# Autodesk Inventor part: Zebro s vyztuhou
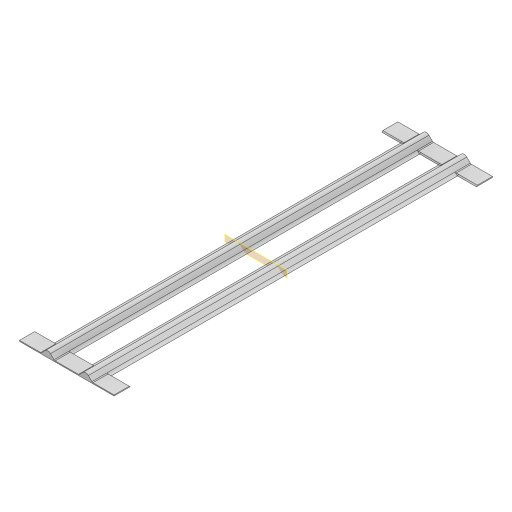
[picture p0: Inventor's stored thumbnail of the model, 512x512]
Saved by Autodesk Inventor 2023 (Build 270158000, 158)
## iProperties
Created: 2025-03
Part Number: Zebro s vyztuhou
Material: Všeobecné
Document SubType Name: Modeling
Designer: tomik
Density: 1 g/cm^3
Appearance: Výchozí
Author: tomik
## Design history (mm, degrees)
sketch "Náčrt1"
  geometry: L1 (10, 0)-(10, 6.192); L2 (10, 0)-(14, 0); L3 (10, 4)-(14, 0); L4 (10, 4)-(6, 0); L5 (10, 0)-(6, 0); L6 (0, 0)-(0, 12.455); L7 (0, 0)-(19.203, 0)
  constraints: 14 end point, 2 horizontal, 2 point on line, 2 vertical, 1 parallel, 1 symmetric about line
  dimensions: "d1" = 4 distance from line of L3.start L2; "d30" = 4 distance of L1.start L2.end; "d31" = 10 distance of L1.start L6.start
extrude "Vysunutí1" new body sketch "Náčrt1" distance "d2" = 200; taper "d3" = 0 deg
sketch "Náčrt2"
  geometry: L1 (0, 0)-(9.652, 0); L2 (14, 0)-(10, 4) reference; L3 (14, 0)-(15.036, 0); A1 r 2.5 centre (15.036, 2.5) between (13.268, 0.732) and (15.036, 0)
  constraints: 4 end point, 3 tangent, 2 point on circle, 2 point on line, 1 centre point, 1 collinear, 1 horizontal
  dimensions: "d4" = 5 diameter of A1
extrude "Vysunutí2" join sketch "Náčrt2" distance "d5" = 200; taper "d6" = 0 deg
fillet "Zaoblení1" dims "d7" = 2
node "Pracovní rovina5"
mirror "Zrcadlit6"
mirror "Zrcadlit8"
sketch "Náčrt10"
  geometry: L1 (30.071, 200)-(30.071, 0) reference; L2 (3.621, 0)-(6.45, 0) reference; L3 (5.036, 0)-(25.036, 0); L4 (25.036, 0)-(25.036, 8.5); L5 (25.036, 8.5)-(5.036, 8.5); L6 (5.036, 8.5)-(5.036, 0); 2 further points
  constraints: 8 end point, 2 parallel, 1 horizontal, 1 midpoint, 1 perpendicular
  dimensions: "d34" = 8.5 distance between parallel lines of L3 L5; "d35" = 20 distance between parallel lines of L4 L6
extrude "Vysunutí9" join sketch "Náčrt10" distance "d36" = 0.5; taper "d37" = 0 deg
fillet "Zaoblení4" dims "d38" = 0.8
node "Pracovní rovina7"
mirror "Zrcadlit9"
chamfer "Zkosení1" distance "d40" = 0.5; stored, may be unused: second distance "d41" = 2, angle "d42" = 45 deg
chamfer "Zkosení2" distance "d43" = 0.5; stored, may be unused: second distance "d44" = 2, angle "d45" = 45 deg
sketch "Náčrt11"
  geometry: L1 (0, 0)-(-30.071, 0) reference; L2 (-10.071, 8.5)-(-20, 8.5) reference; L3 (-3.621, 0)-(-6.45, 0) reference; L4 (-5.036, 0)-(9.964, 0); L5 (9.964, 0)-(9.964, 8.5); L6 (9.964, 8.5)-(-5.036, 8.5); L7 (-5.036, 8.5)-(-5.036, 0); 4 further points
  constraints: 8 end point, 2 midpoint, 2 perpendicular, 1 point on line
  dimensions: "d50" = 15 distance of L4.start L4.end; "d51" = 8.5 distance of L4.end L5.end; "d52" = 15 distance of L5.end L6.end
extrude "Vysunutí11" join sketch "Náčrt11" distance "d53" = 0.5; taper "d54" = 0 deg
fillet "Zaoblení5" dims "d55" = 0.8
chamfer "Zkosení3" distance "d56" = 0.5; stored, may be unused: second distance "d57" = 2, angle "d58" = 45 deg
mirror "Zrcadlit12"
fillet "Zaoblení6" dims "d59" = 0.8
chamfer "Zkosení4" distance "d60" = 0.5; stored, may be unused: second distance "d61" = 2, angle "d62" = 45 deg
mirror "Zrcadlit13"
fillet "Zaoblení7" dims "d63" = 0.8
chamfer "Zkosení5" distance "d64" = 0.5; stored, may be unused: second distance "d65" = 2, angle "d66" = 45 deg
node "Těleso1"
